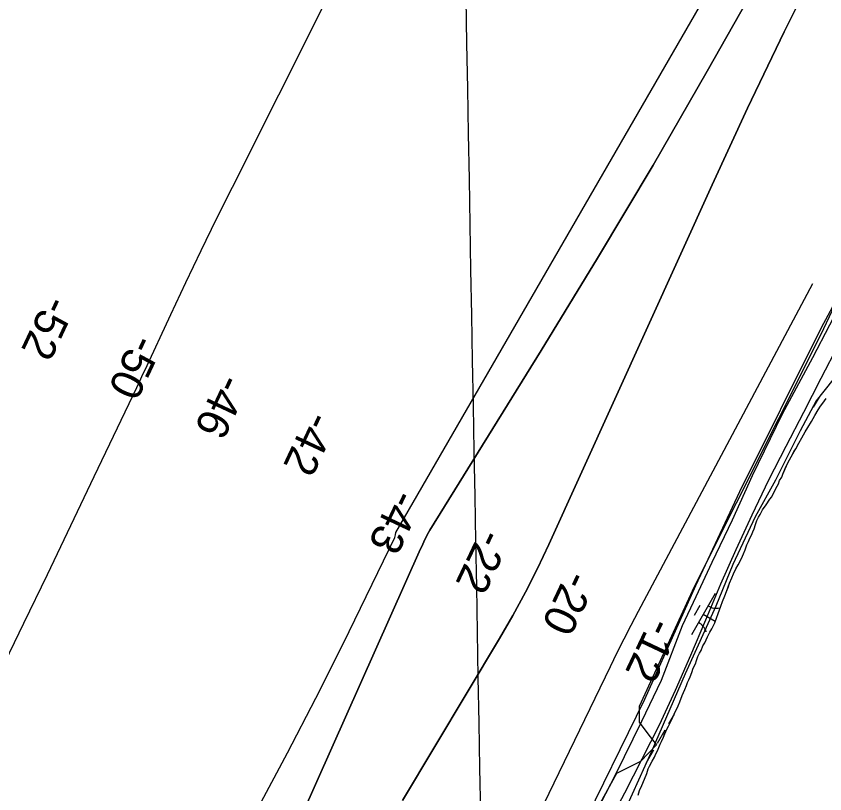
# Model space of a CAD drawing. Extents: x 3930721 to 3950824, y 220441 to 242861.
# Drawn here: x 3940311 to 3941157, y 228013 to 228826 of the extents above; entities that cross this region are included whole.
import ezdxf

# ---------------------------------------------------------------- set-up
doc = ezdxf.new("R2010")
doc.units = 0
for name, color, linetype in [('V-GRID-MAJR', 7, 'Continuous'), ('V-RIVR-EDGE', 7, 'Continuous'), ('V-RIVR-JETY', 7, 'Continuous'), ('V-RIVR-RANG', 7, 'Continuous'), ('V-RRAP-FSHR', 7, 'Continuous'), ('V-TOPO-DPTH', 7, 'Continuous'), ('V-TOPO-MAJR', 7, 'Continuous'), ('V-TOPO-MINR', 7, 'Continuous'), ('V-TOPO-SHOR', 7, 'Continuous'), ('V-WETL-SWMP', 7, 'Continuous')]:
    doc.layers.add(name, color=color, linetype=linetype)

msp = doc.modelspace()

# ---------------------------------------------------------------- linework, layer by layer
at = {"layer": 'V-GRID-MAJR'}
msp.add_spline([(3940914.45, 221486.32), (3940866.25, 224158.18), (3940756.95, 230218.14), (3940647.64, 236278.08), (3940604.74, 238656.84)], degree=3, dxfattribs=at)
at = {"layer": 'V-RIVR-EDGE'}
msp.add_lwpolyline([(3941301.09, 228775.91), (3941296.4, 228758.85), (3941299.55, 228743.89), (3941308.99, 228729.72), (3941313.72, 228716.34), (3941313.72, 228698.24), (3941308.99, 228680.13), (3941297.97, 228664.39), (3941283.02, 228654.94), (3941257.83, 228642.35), (3941239.72, 228635.26), (3941222.41, 228624.24), (3941202.73, 228599.84), (3941152.35, 228492.79), (3941020.11, 228229.88), (3940962.64, 228104.72), (3940962.64, 228088.19), (3940972.88, 228074.81), (3940980.75, 228064.57), (3940964.22, 228047.25), (3940939.03, 228034.66), (3940807.57, 227796.15)], dxfattribs=at)
at = {"layer": 'V-RIVR-JETY'}
for points in [[(3940906.97, 227973.2), (3940938.21, 228034.07), (3940965.56, 228089.4), (3940985.97, 228132.08), (3941008.2, 228189.32), (3941022.45, 228219.74), (3941038.99, 228255.7), (3941060.17, 228299.96), (3941081.33, 228346.18), (3941112.53, 228410.59), (3941144.18, 228469.5), (3941180.06, 228537.9), (3941217.5, 228607.49), (3941248.38, 228664.82), (3941269.21, 228703.96), (3941291.6, 228745.87), (3941326.68, 228815.04), (3941363.35, 228883.05)], [(3941387.01, 228876.6), (3941347.68, 228799.13), (3941314.88, 228737.85), (3941292.89, 228696.33), (3941277.5, 228661.97), (3941266.71, 228640.62), (3941241.19, 228597.89), (3941208.78, 228536.61), (3941186.1, 228485.26), (3941165.26, 228446.12), (3941147.78, 228424.32), (3941131.19, 228392.69), (3941105.37, 228341.31), (3941084.13, 228302.95), (3941060.64, 228253.16), (3941043, 228209.73), (3941010.68, 228139.01), (3940975.33, 228056.86), (3940948.79, 227998.39)]]:
    msp.add_lwpolyline(points, dxfattribs=at)
at = {"layer": 'V-RRAP-FSHR'}
msp.add_lwpolyline([(3940928.81, 227978.99), (3940947.58, 228014.31), (3940965.95, 228049.84), (3940983.89, 228085.59), (3941000.7, 228121.88), (3941016.91, 228158.45), (3941032.56, 228195.26), (3941048.16, 228232.92), (3941064.11, 228268.77), (3941080.77, 228305.13), (3941098.32, 228341.69), (3941116.62, 228376.64), (3941134.91, 228412.21), (3941153.2, 228447.79), (3941171.49, 228483.36)], dxfattribs=at)
at = {"layer": 'V-TOPO-DPTH'}
for points in [[(3941681.59, 229966.31), (3941338.17, 229249.76), (3941327.99, 229228.71), (3941317.7, 229207.72), (3941307.26, 229186.79), (3941296.72, 229165.92), (3941286.08, 229145.1), (3941275.39, 229124.3), (3941264.65, 229103.53), (3941253.87, 229082.78), (3941193.79, 228967.53), (3941153.58, 228888.86), (3941114.24, 228809.77), (3941076.18, 228730.04), (3941038.99, 228649.9), (3940868.17, 228273.87), (3940856.26, 228248.8), (3940843.8, 228224.03), (3940830.5, 228199.7), (3940816.64, 228175.66), (3940715.12, 228006.28)], [(3940564.46, 227999.47), (3940595.11, 228056.12), (3940624.65, 228113.35), (3940653.45, 228170.98), (3940707.26, 228281.31), (3940708.02, 228284), (3940708.19, 228286.63), (3941049.01, 228876.88), (3941078.54, 228921.67), (3941107.23, 228966.97), (3941134.67, 229013.05), (3941161.28, 229059.63), (3941203.6, 229136.16), (3941208.33, 229144.91), (3941212.97, 229153.71), (3941217.45, 229162.59), (3941221.82, 229171.53), (3941534.21, 229824.03)], [(3940564.46, 227999.47), (3940595.11, 228056.12), (3940624.65, 228113.35), (3940653.45, 228170.98), (3940707.26, 228281.31), (3940708.02, 228284), (3940708.19, 228286.63), (3941049.01, 228876.88), (3941078.54, 228921.67), (3941107.23, 228966.97), (3941134.67, 229013.05), (3941161.28, 229059.63), (3941203.6, 229136.16), (3941208.33, 229144.91), (3941212.97, 229153.71), (3941217.45, 229162.59), (3941221.82, 229171.53), (3941534.21, 229824.03)], [(3940578.46, 227920.88), (3940734.15, 228269.41), (3940735.27, 228271.9), (3940736.39, 228274.4), (3940737.52, 228276.89), (3940738.65, 228279.38), (3940739.82, 228281.84), (3940741.06, 228284.27), (3940742.4, 228286.65), (3940743.79, 228289), (3940860.28, 228476.79), (3940919.25, 228573.43), (3940977.26, 228670.64), (3941033.83, 228768.68), (3941089.44, 228867.29)], [(3941089.44, 228867.29), (3941033.83, 228768.68), (3940977.26, 228670.64), (3940919.25, 228573.43), (3940860.28, 228476.79), (3940743.79, 228289), (3940742.4, 228286.65), (3940741.06, 228284.27), (3940739.82, 228281.84), (3940738.65, 228279.38), (3940737.52, 228276.89), (3940736.39, 228274.4), (3940735.27, 228271.9), (3940734.15, 228269.41), (3940578.46, 227920.88)]]:
    msp.add_lwpolyline(points, dxfattribs=at)
at = {"layer": 'V-TOPO-MAJR'}
msp.add_lwpolyline([(3940294.46, 228140.71), (3940319.25, 228191.69), (3940343.94, 228242.72), (3940368.48, 228293.82), (3940392.92, 228344.97), (3940437.26, 228438.09), (3940439.45, 228442.71), (3940441.64, 228447.34), (3940443.81, 228451.97), (3940445.98, 228456.61), (3940472.89, 228514.39), (3940488.66, 228547.85), (3940504.62, 228581.22), (3940520.88, 228614.44), (3940537.33, 228647.56), (3940876.08, 229322.03), (3940884.09, 229337.02), (3940892.6, 229351.72), (3940901.83, 229365.96), (3940911.55, 229379.91), (3941148.95, 229702.79)], dxfattribs=at)
at = {"layer": 'V-TOPO-MINR'}
for points in [[(3940715.12, 228006.28), (3940816.64, 228175.66), (3940830.5, 228199.7), (3940843.8, 228224.03), (3940856.26, 228248.8), (3940868.17, 228273.87), (3941038.99, 228649.9), (3941076.18, 228730.04), (3941114.24, 228809.77), (3941153.58, 228888.86), (3941193.79, 228967.53), (3941253.87, 229082.78), (3941264.65, 229103.53), (3941275.39, 229124.3), (3941286.08, 229145.1), (3941296.72, 229165.92), (3941307.26, 229186.79), (3941317.7, 229207.72), (3941327.99, 229228.71), (3941338.17, 229249.76), (3941681.59, 229966.31)], [(3940564.46, 227999.47), (3940595.11, 228056.12), (3940624.65, 228113.35), (3940653.45, 228170.98), (3940707.26, 228281.31), (3940708.02, 228284), (3940708.19, 228286.63), (3941049.01, 228876.88), (3941078.54, 228921.67), (3941107.23, 228966.97), (3941134.67, 229013.05), (3941161.28, 229059.63), (3941203.6, 229136.16), (3941208.33, 229144.91), (3941212.97, 229153.71), (3941217.45, 229162.59), (3941221.82, 229171.53), (3941534.21, 229824.03)], [(3940578.46, 227920.88), (3940734.15, 228269.41), (3940735.27, 228271.9), (3940736.39, 228274.4), (3940737.52, 228276.89), (3940738.65, 228279.38), (3940739.82, 228281.84), (3940741.06, 228284.27), (3940742.4, 228286.65), (3940743.79, 228289), (3940860.28, 228476.79), (3940919.25, 228573.43), (3940977.26, 228670.64), (3941033.83, 228768.68), (3941089.44, 228867.29)], [(3940766.83, 227803.88), (3940932.59, 228146.52), (3940939.72, 228161.03), (3940946.95, 228175.49), (3940954.36, 228189.86), (3940961.87, 228204.17), (3941144.27, 228546.71)]]:
    msp.add_lwpolyline(points, dxfattribs=at)
at = {"layer": 'V-TOPO-SHOR'}
for points in [[(3941003.42, 228105.24), (3941005.12, 228109.45), (3941007.85, 228116.12), (3941010.58, 228122.43), (3941012.29, 228126.65), (3941013.31, 228129.8), (3941014.68, 228132.61), (3941016.04, 228135.77), (3941017.75, 228140.33), (3941019.1, 228144.89), (3941021.5, 228149.46), (3941022.52, 228152.62), (3941024.22, 228156.83), (3941025.93, 228160.34), (3941027.65, 228163.15), (3941029.35, 228168.06), (3941031.41, 228171.23), (3941032.78, 228174.39), (3941034.15, 228177.55), (3941036.54, 228182.47), (3941038.6, 228185.98), (3941041.69, 228192.31), (3941045.43, 228201.78), (3941048.15, 228209.5), (3941049.85, 228214.41), (3941052.24, 228220.37), (3941053.94, 228224.94), (3941055.98, 228230.2), (3941057.35, 228233.71), (3941059.73, 228239.33), (3941061.44, 228243.19), (3941063.84, 228248.45), (3941066.24, 228252.67), (3941069.67, 228259.35), (3941071.72, 228264.26), (3941073.42, 228268.47), (3941075.47, 228273.74), (3941077.18, 228277.25), (3941078.54, 228280.76), (3941080.25, 228283.92), (3941081.62, 228287.43), (3941082.99, 228290.24), (3941084.34, 228294.8), (3941085.7, 228299.01), (3941087.41, 228302.52), (3941089.13, 228305.33), (3941091.87, 228310.25), (3941095.66, 228315.53), (3941099.45, 228321.52), (3941101.52, 228323.98), (3941104.26, 228329.6), (3941105.63, 228332.41), (3941108.38, 228337.33), (3941109.39, 228340.84), (3941111.8, 228344.36), (3941112.81, 228347.52), (3941115.55, 228353.49), (3941118.29, 228359.46), (3941121.72, 228365.78), (3941124.81, 228371.41), (3941126.53, 228373.87), (3941129.62, 228379.84), (3941132.7, 228385.46), (3941136.48, 228391.8), (3941139.23, 228396.37), (3941143.02, 228402.7), (3941146.45, 228409.02), (3941149.88, 228414.65), (3941152.29, 228418.52), (3941154.71, 228421.69), (3941158.15, 228426.62)], [(3940961.72, 228012.19), (3940963.07, 228016.75), (3940965.47, 228022.02), (3940968.19, 228028.68), (3940970.58, 228034.65), (3940972.28, 228039.56), (3940973.65, 228042.37), (3940976.39, 228047.64), (3940978.79, 228051.86), (3940980.16, 228055.37), (3940981.87, 228058.53), (3940984.6, 228065.2), (3940985.97, 228068.01), (3940988.02, 228072.58), (3940989.38, 228076.08), (3940991.78, 228081), (3940993.5, 228084.16), (3940996.24, 228089.78), (3940997.95, 228093.65), (3941000.33, 228099.26), (3941002.05, 228102.43), (3941003.42, 228105.24)]]:
    msp.add_lwpolyline(points, dxfattribs=at)
at = {"layer": 'V-WETL-SWMP'}
for p, q in [((3941150.81, 228427.95), (3941144.84, 228417.53)), ((3941042.23, 228222.83), (3941017.38, 228179.44)), ((3941026.09, 228210.18), (3941020.13, 228199.77)), ((3941029.8, 228201.14), (3941042.34, 228193.96)), ((3940999.3, 228096.82), (3940993.52, 228086.74)), ((3940989.55, 228079.8), (3940981.6, 228065.92)), ((3940977.62, 228058.98), (3940969.67, 228045.09))]:
    msp.add_line(p, q, dxfattribs=at)
for points in [[(3941759.88, 229782.48), (3941694.26, 229632.9), (3941629.26, 229484.54), (3941548.34, 229295.89), (3941481.78, 229140.52), (3941419.41, 229008.99), (3941326.77, 228826), (3941257.89, 228692.08), (3941204.73, 228595.87), (3941153.2, 228500.39), (3941067.67, 228329.19), (3941021.76, 228230.96), (3940968.37, 228111.89), (3940899.56, 227971.9)], [(3940961.72, 228012.19), (3940963.07, 228016.75), (3940965.47, 228022.02), (3940968.19, 228028.68), (3940970.58, 228034.65), (3940972.28, 228039.56), (3940973.65, 228042.37), (3940976.39, 228047.64), (3940978.79, 228051.86), (3940980.16, 228055.37), (3940981.87, 228058.53), (3940984.6, 228065.2), (3940985.97, 228068.01), (3940988.02, 228072.58), (3940989.39, 228076.08), (3940991.78, 228081), (3940993.5, 228084.16), (3940996.24, 228089.78), (3940997.95, 228093.65), (3941000.33, 228099.26), (3941002.05, 228102.43), (3941003.42, 228105.24), (3941005.13, 228109.45), (3941007.85, 228116.12), (3941010.59, 228122.43), (3941012.29, 228126.65), (3941013.31, 228129.8), (3941014.68, 228132.61), (3941016.04, 228135.77), (3941017.75, 228140.33), (3941019.1, 228144.89), (3941021.5, 228149.46), (3941022.51, 228152.61), (3941024.22, 228156.83), (3941025.93, 228160.34), (3941027.65, 228163.15), (3941029.35, 228168.06), (3941031.41, 228171.23), (3941034.15, 228177.55), (3941036.54, 228182.47), (3941038.6, 228185.98), (3941041.69, 228192.31), (3941045.44, 228201.78), (3941048.15, 228209.5), (3941049.85, 228214.41), (3941052.24, 228220.37), (3941053.94, 228224.94), (3941057.35, 228233.71), (3941059.73, 228239.33), (3941061.44, 228243.19), (3941063.84, 228248.45), (3941066.24, 228252.67), (3941069.67, 228259.35), (3941071.72, 228264.26), (3941073.42, 228268.47), (3941075.46, 228273.74), (3941077.18, 228277.25), (3941078.54, 228280.76), (3941080.25, 228283.92), (3941081.62, 228287.43), (3941082.99, 228290.24), (3941084.34, 228294.8), (3941085.7, 228299.01), (3941087.41, 228302.52), (3941089.13, 228305.33), (3941091.87, 228310.25), (3941095.66, 228315.54), (3941099.45, 228321.52), (3941101.52, 228323.98), (3941105.63, 228332.41), (3941108.38, 228337.33), (3941109.39, 228340.84), (3941111.8, 228344.36), (3941112.82, 228347.52), (3941118.29, 228359.46), (3941121.72, 228365.78), (3941124.81, 228371.4), (3941126.53, 228373.87), (3941129.62, 228379.84), (3941132.7, 228385.47), (3941136.48, 228391.8), (3941139.23, 228396.37), (3941143.02, 228402.7), (3941146.45, 228409.02), (3941149.89, 228414.65), (3941152.29, 228418.52), (3941154.71, 228421.69), (3941158.15, 228426.62)]]:
    msp.add_lwpolyline(points, dxfattribs=at)
for centre, start, end in [((3941043.74, 228224.99), 239.42788, 280.97154), ((3941016.28, 228177.05), 19.42788, 60.97154)]:
    msp.add_arc(centre, 17.62, start, end, dxfattribs=at)

# ---------------------------------------------------------------- texts
at = {"layer": 'V-RIVR-RANG'}
for s, rotation, p in [('-52', 244.84019, (3940343.34, 228536.13)), ('-50', 244.84019, (3940434.39, 228495.32)), ('-46', 244.84019, (3940524.76, 228454.23)), ('-42', 244.84019, (3940617.41, 228415.16)), ('-43', 244.69833, (3940706.68, 228333.43)), ('-22', 244.69833, (3940797.75, 228292.1)), ('-20', 244.69833, (3940887.87, 228248.76)), ('-12', 244.69833, (3940975.17, 228199.44))]:
    msp.add_text(s, height=33.5, rotation=rotation, dxfattribs=at).set_placement(p)

doc.saveas('drawing.dxf')
